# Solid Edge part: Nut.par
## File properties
Author: CADCIM
Template: NORMENG.PAR
Last saved by: CADCIM
Revision: 3
Application: Solid Edge
Density: 0 lbm/in^3
Accuracy: 0.99
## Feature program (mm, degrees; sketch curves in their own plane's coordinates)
sketch for "unnamed Protrusion 1" plane through (0, 0, 0) normal (0, 0, 1) x-axis (1, 0, 0)
  line (-2.5663, 4.445) -> (2.5663, 4.445)
  line (2.5663, 4.445) -> (5.1326, 0)
  line (5.1326, 0) -> (2.5663, -4.445)
  line (2.5663, -4.445) -> (-2.5663, -4.445)
  line (-2.5663, -4.445) -> (-5.1326, 0)
  line (-5.1326, 0) -> (-2.5663, 4.445)
extrude "unnamed Protrusion 1" add finite 5.08 symmetric
sketch for "unnamed RevolvedCutout 1" plane through (0, 0, 0) normal (0, -1, 0) x-axis (1, 0, 0)
  line (4.445, 2.54) -> (5.1326, 2.143)
revolve "unnamed RevolvedCutout 1" cut finite 360 deg
mirror "unnamed Mirror 1" of "unnamed RevolvedCutout 1" about plane through (0, 0, 0) normal (0, 0, 1)
revolve "unnamed RevolvedCutout 2" cut finite 360 deg
sketch for "Hole_1" plane through (0, 0, 2.54) normal (0, 0, 1) x-axis (1, 0, 0)
  hole centre (0, 0) bore radius 3.175
hole "Hole_1" diameter 6.35 through
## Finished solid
Body 1: solid body, 21 faces, 44 edges, 24 vertices.
  Faces by surface: cone 12, plane 8, cylinder 1
  Edges by curve: intersection 24, circle 14, line 6
Bounding box of the edges (mm): 10.265 x 8.890 x 5.080, from (-5.1326, -4.445, -2.54) to (5.1326, 4.445, 2.54).
Cylindrical faces by radius (mm): R3.175 x1
Conical faces (half-angle, radius in mm at the cone's reference point): 60 deg R4.445 x6, 60 deg R5.1326 x6
Planar faces by outward normal: +y 1, +z 1, -y 1, -z 1, oblique 4
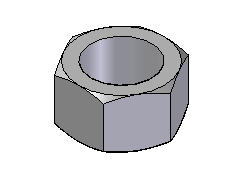
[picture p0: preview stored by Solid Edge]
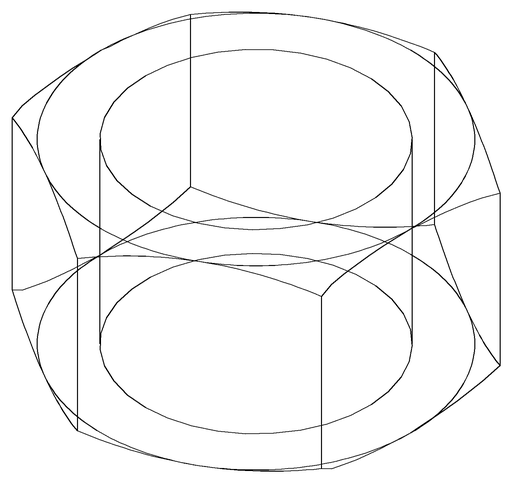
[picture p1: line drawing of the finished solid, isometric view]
